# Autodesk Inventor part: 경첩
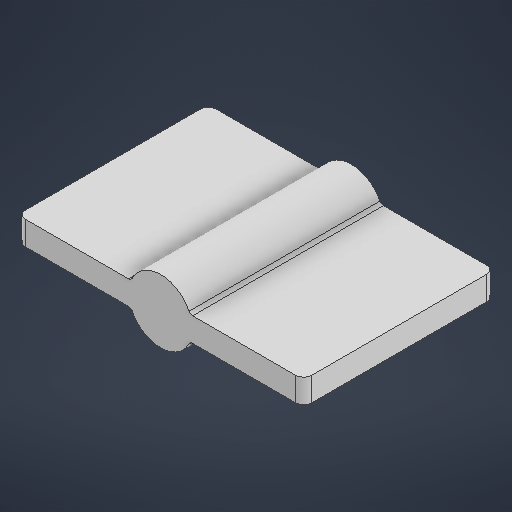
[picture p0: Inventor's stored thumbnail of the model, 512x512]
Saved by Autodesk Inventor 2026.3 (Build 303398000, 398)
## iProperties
Created: 2026-08
Part Number: 경첩
Material: 일반
Document SubType Name: Modeling
Designer: chang
Density: 1 g/cm^3
Appearance: 기본값
Author: chang
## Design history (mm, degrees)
sketch "스케치1"
  geometry: L1 (4, -1.5)-(18, -1.5); L2 (18, -1.5)-(18, 1.5); L3 (18, 1.5)-(4, 1.5); L4 (-4, -1.5)-(-18, -1.5) reference; L5 (-18, -1.5)-(-18, 1.5); L6 (-18, 1.5)-(-4, 1.5); L7 (-4, -1.5)-(-3.708, -1.5); L8 (-4, 1.5)-(-3.708, 1.5); L9 (4, 1.5)-(3.708, 1.5); L10 (4, -1.5)-(3.708, -1.5); A1 r 4 centre (0, 0) between (-3.708, -1.5) and (3.708, -1.5); A2 r 4 centre (0, 0) between (3.708, 1.5) and (-3.708, 1.5); A3 r 4 centre (0, 0) between (-3.708, 1.5) and (-3.708, -1.5); A4 r 4 centre (0, 0) between (3.708, -1.5) and (3.708, 1.5); 1 further point
  constraints: 20 end point, 8 point on circle, 4 centre point, 4 perpendicular, 3 coincident, 3 horizontal, 3 parallel
  dimensions: "d3" = 14 distance of L1.start L1.end; "d6" = 14 distance of L4.start L4.end; "d7" = 3 distance between parallel lines of L4 L8; "d8" = 3 distance between parallel lines of L3 L4; "d9" = 0 distance between parallel lines of L10 L4; "d10" = 36 distance between parallel lines of L2 L5; "d11" = 18 distance from line of point (0, 0) L2; "d12" = 14 distance from line of L3.end L2; "d13" = 22 distance from line of L6.end L2; "d14" = 4 radius of A2
extrude "돌출1" new body sketch "스케치1" distance "d15" = 24; taper "d16" = 0 deg
fillet "모깎기1" dims "d17" = 1
fillet "모깎기2" dims "d18" = 1
fillet "모깎기3" dims "d19" = 1
fillet "모깎기4" dims "d20" = 1
feature "면 모깎기1" dims "d21" = 0.5
feature "면 모깎기2" dims "d22" = 0.5
feature "면 모깎기3" dims "d23" = 0.5
feature "면 모깎기4" dims "d24" = 0.5
node "솔리드1"
other parameters: "d0" = 8
